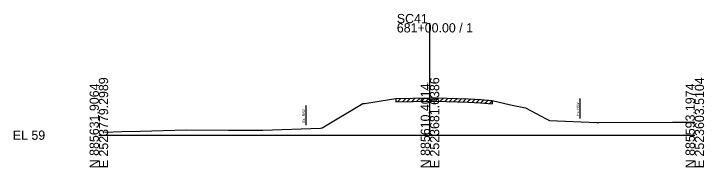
# Model space of a CAD drawing. Extents: x -26 to 183, y -10 to 24021.
# Drawn here: x -25.7 to 182.8, y 12490.3 to 12536.7 of the extents above; entities that cross this region are included whole.
import ezdxf

# ---------------------------------------------------------------- set-up
doc = ezdxf.new("R2010")
doc.units = 0
for name, color, linetype in [('RD_GPK_XS_Cell', 7, 'Continuous'), ('RD_XS_ExGround', 7, 'Continuous'), ('RD_XS_ExPaveRet', 7, 'Continuous'), ('RD_XS_ExRW', 7, 'Continuous'), ('RD_XS_TX_Elev_EX', 7, 'Continuous')]:
    doc.layers.add(name, color=color, linetype=linetype)

msp = doc.modelspace()

# ---------------------------------------------------------------- linework, layer by layer
at = {"layer": 'RD_GPK_XS_Cell'}
for p, q in [((100, 12500), (100, 12533.86)), ((0, 12500), (100, 12500)), ((100, 12500), (180, 12500))]:
    msp.add_line(p, q, dxfattribs=at)
at = {"layer": 'RD_XS_ExGround'}
for p, q in [((80.19, 12509.61), (89.74, 12511.07)), ((89.74, 12511.07), (100, 12511.27)), ((100, 12511.27), (100.52, 12511.28)), ((100.52, 12511.28), (101.05, 12511.29)), ((101.05, 12511.29), (101.75, 12511.27)), ((101.75, 12511.27), (111.67, 12511.02)), ((111.67, 12511.02), (115.4, 12510.74)), ((115.4, 12510.74), (118.79, 12510.47)), ((118.79, 12510.47), (124.34, 12509.22)), ((67.42, 12502.17), (79.73, 12509.54)), ((79.73, 12509.54), (80.19, 12509.61)), ((124.34, 12509.22), (128.9, 12508.22)), ((128.9, 12508.22), (135.08, 12504.97)), ((135.08, 12504.97), (136.15, 12504.4)), ((136.15, 12504.4), (150.48, 12503.87)), ((150.48, 12503.87), (150.9, 12503.86)), ((150.9, 12503.86), (173.3, 12503.97)), ((173.3, 12503.97), (180, 12503.92)), ((12.53, 12501.21), (26.32, 12501.59)), ((26.32, 12501.59), (39.11, 12501.55)), ((39.11, 12501.55), (49.51, 12501.52)), ((49.51, 12501.52), (66.99, 12502.16)), ((66.99, 12502.16), (67.42, 12502.17)), ((1.78, 12500.92), (6.98, 12501.14)), ((6.98, 12501.14), (12.53, 12501.21))]:
    msp.add_line(p, q, dxfattribs=at)
at = {"layer": 'RD_XS_ExPaveRet'}
for p, q in [((89.74, 12511.01), (89.81, 12511.08)), ((89.74, 12511.07), (89.74, 12510.07)), ((89.74, 12510.07), (100, 12510.27)), ((90.23, 12510.08), (91.25, 12511.1)), ((91.67, 12510.11), (92.69, 12511.13)), ((93.11, 12510.14), (94.13, 12511.16)), ((94.55, 12510.17), (95.57, 12511.18)), ((95.99, 12510.19), (97.01, 12511.21)), ((97.44, 12510.22), (98.46, 12511.24)), ((98.88, 12510.25), (99.9, 12511.27)), ((100, 12510.27), (100.54, 12510.28)), ((100.32, 12510.27), (101.33, 12511.28)), ((100.54, 12510.28), (101.05, 12510.29)), ((101.05, 12510.29), (101.72, 12510.27)), ((101.72, 12510.27), (111.62, 12510.02)), ((101.73, 12510.27), (102.71, 12511.25)), ((103.11, 12510.24), (104.09, 12511.21)), ((104.49, 12510.2), (105.47, 12511.18)), ((105.87, 12510.17), (106.85, 12511.14)), ((107.25, 12510.13), (108.23, 12511.11)), ((108.63, 12510.1), (109.61, 12511.07)), ((110.01, 12510.06), (110.99, 12511.04)), ((111.39, 12510.03), (112.33, 12510.97)), ((111.62, 12510.02), (115.32, 12509.74)), ((112.71, 12509.94), (113.64, 12510.87)), ((114.03, 12509.84), (114.96, 12510.77)), ((115.34, 12509.74), (116.27, 12510.67)), ((116.65, 12509.63), (117.58, 12510.56)), ((117.96, 12509.53), (118.79, 12510.36)), ((118.79, 12510.47), (118.79, 12509.46)), ((115.32, 12509.74), (118.79, 12509.46))]:
    msp.add_line(p, q, dxfattribs=at)
at = {"layer": 'RD_XS_ExRW'}
for p, q in [((145.32, 12511.06), (145.32, 12505.06)), ((62.5, 12508.99), (62.5, 12502.99))]:
    msp.add_line(p, q, dxfattribs=at)

# ---------------------------------------------------------------- texts
at = {"layer": 'RD_GPK_XS_Cell'}
for s, p in [('SC41', (90, 12533.86)), ('681+00.00 / 1', (90, 12531.06)), ('EL 59', (-26, 12498.6))]:
    msp.add_text(s, height=2.8, dxfattribs=at).set_placement(p)
for s, p in [('E 2523779.2989', (2.8, 12490)), ('E 2523681.6386', (102.8, 12490)), ('E 2523603.5104', (182.8, 12490)), ('N 885631.9064', (0, 12490)), ('N 885610.4014', (100, 12490)), ('N 885593.1974', (180, 12490))]:
    msp.add_text(s, height=2.8, rotation=90, dxfattribs=at).set_placement(p)
at = {"layer": 'RD_XS_ExRW'}
for p in [(145.07, 12505.85), (62.25, 12503.78)]:
    msp.add_text('Ex. R/W ', height=0.8, rotation=90, dxfattribs=at).set_placement(p)
at = {"layer": 'RD_XS_TX_Elev_EX'}
msp.add_text('70.27', height=0.8, rotation=90, dxfattribs=at).set_placement((99.9, 12513.27))

doc.saveas('drawing.dxf')
